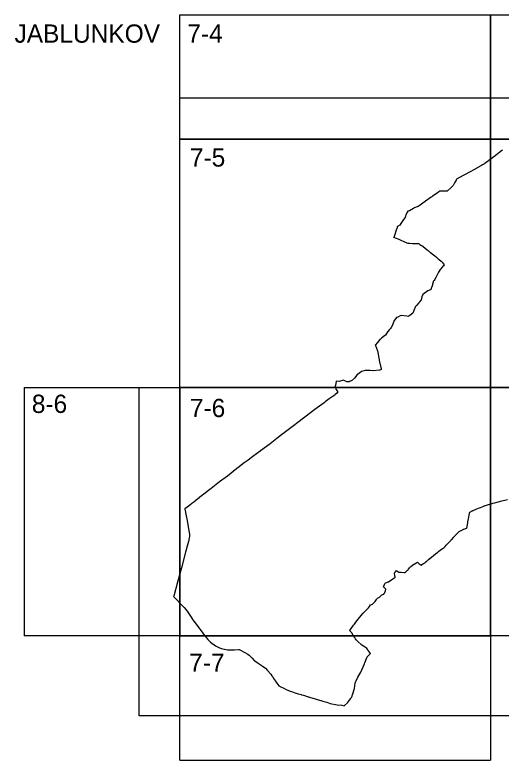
# Model space of a CAD drawing. Extents: x -449577 to -436680, y -1132317 to -1125726.
# Drawn here: x -441662.8 to -441418.4, y -1131943.6 to -1131568.6 of the extents above; entities that cross this region are included whole.
import ezdxf

# ---------------------------------------------------------------- set-up
doc = ezdxf.new("R2010")
doc.units = 0
for name, color, linetype in [('Vrstva 1', 7, 'Continuous'), ('Vrstva 10', 7, 'Continuous'), ('Vrstva 4', 7, 'Continuous')]:
    doc.layers.add(name, color=color, linetype=linetype)

msp = doc.modelspace()

# ---------------------------------------------------------------- linework, layer by layer
at = {"layer": 'Vrstva 1'}
for points in [[(-441417.64, -1131636.64), (-441418.85, -1131637.6), (-441418.85, -1131637.6), (-441420, -1131638.47), (-441420.57, -1131638.9), (-441421.15, -1131639.34), (-441421.31, -1131639.46), (-441423.44, -1131641.1), (-441424.51, -1131641.92), (-441424.98, -1131642.26), (-441425.74, -1131642.77), (-441425.99, -1131642.93), (-441426.58, -1131643.32), (-441426.62, -1131643.35), (-441426.83, -1131643.49), (-441427.74, -1131644.09), (-441427.75, -1131644.09), (-441428.22, -1131644.35), (-441428.37, -1131644.43), (-441428.55, -1131644.53), (-441429.01, -1131644.78), (-441429.19, -1131644.89), (-441429.35, -1131644.98), (-441429.45, -1131645.04), (-441429.69, -1131645.18), (-441431.35, -1131646.12), (-441431.52, -1131646.21), (-441431.75, -1131646.34), (-441434.22, -1131647.74), (-441434.34, -1131647.81), (-441436.45, -1131648.94), (-441437.47, -1131649.49), (-441440.81, -1131651.3), (-441440.98, -1131651.6), (-441441.04, -1131651.71), (-441441.82, -1131653.17), (-441442.5, -1131654.49), (-441442.64, -1131654.62), (-441442.73, -1131654.7), (-441443.87, -1131655.74), (-441445.38, -1131657.12), (-441445.55, -1131657.27), (-441445.55, -1131657.28), (-441446.02, -1131657.29), (-441449.21, -1131657.38), (-441449.22, -1131657.38), (-441449.65, -1131657.67), (-441450.48, -1131658.24), (-441452.95, -1131659.9), (-441452.99, -1131659.92), (-441453.23, -1131660.1), (-441453.5, -1131660.3), (-441456.48, -1131662.43), (-441456.55, -1131662.48), (-441459.55, -1131664.66), (-441460.02, -1131665), (-441460.18, -1131665.06), (-441462.12, -1131665.78), (-441462.13, -1131665.78), (-441462.52, -1131666.02), (-441464.4, -1131667.18), (-441465.32, -1131667.39), (-441465.57, -1131667.9), (-441466.33, -1131669.41), (-441466.34, -1131669.42), (-441466.41, -1131669.68), (-441466.61, -1131670.52), (-441467.44, -1131671.63), (-441468.81, -1131673.58), (-441469.37, -1131674.39), (-441469.4, -1131674.41), (-441470.56, -1131675.05), (-441470.66, -1131675.11), (-441470.73, -1131675.5), (-441470.88, -1131676.31), (-441470.93, -1131676.5), (-441472.22, -1131680.08), (-441472.39, -1131680.56), (-441472.36, -1131680.55), (-441472.34, -1131680.54), (-441471.66, -1131680.8), (-441469.85, -1131681.46), (-441469.23, -1131681.75), (-441466.94, -1131682.83), (-441466.92, -1131682.83), (-441465.76, -1131683.3), (-441465.29, -1131683.48), (-441465.26, -1131683.49), (-441464.83, -1131683.52), (-441464.69, -1131683.53), (-441464.47, -1131683.55), (-441462.87, -1131683.65), (-441461.83, -1131683.72), (-441460.78, -1131683.69), (-441459.94, -1131683.66), (-441459.93, -1131683.66), (-441459.65, -1131683.81), (-441459.28, -1131684.07), (-441458.73, -1131684.45), (-441458.34, -1131684.73), (-441456.78, -1131685.87), (-441456.61, -1131685.99), (-441455.5, -1131686.91), (-441455.11, -1131687.23), (-441454.93, -1131687.38), (-441454.18, -1131687.99), (-441453.91, -1131688.22), (-441453.31, -1131688.71), (-441453.09, -1131688.89), (-441452.45, -1131689.31), (-441451.7, -1131689.81), (-441451.67, -1131689.83), (-441450.91, -1131690.51), (-441450.03, -1131691.29), (-441449.59, -1131691.67), (-441448.58, -1131692.56), (-441448.32, -1131692.79), (-441448.27, -1131692.84), (-441448.17, -1131692.94), (-441448.16, -1131692.95), (-441448.07, -1131693.05), (-441448.04, -1131693.08), (-441446.99, -1131694.31), (-441447, -1131694.32), (-441447.44, -1131694.81), (-441447.5, -1131694.88), (-441448.07, -1131695.51), (-441448.89, -1131696.57), (-441449.06, -1131696.78), (-441449.62, -1131697.5), (-441449.92, -1131698.03), (-441449.94, -1131698.07), (-441449.95, -1131698.09), (-441450.08, -1131698.37), (-441450.88, -1131700.04), (-441451.19, -1131700.68), (-441451.81, -1131701.97), (-441451.92, -1131702.21), (-441451.93, -1131702.21), (-441451.97, -1131702.24), (-441452.26, -1131702.44), (-441452.34, -1131702.48), (-441452.39, -1131702.58), (-441452.48, -1131702.78), (-441452.57, -1131703.06), (-441452.74, -1131703.62), (-441452.75, -1131703.64), (-441452.87, -1131704.14), (-441452.89, -1131704.21), (-441452.88, -1131704.27), (-441452.87, -1131704.35), (-441452.87, -1131704.42), (-441452.88, -1131704.47), (-441453.76, -1131706.8), (-441453.78, -1131706.85), (-441453.8, -1131706.89), (-441453.81, -1131706.9), (-441454.51, -1131707.2), (-441454.76, -1131707.31), (-441455.23, -1131707.55), (-441457.84, -1131709.24), (-441457.84, -1131709.24), (-441458.21, -1131710.55), (-441458.29, -1131710.81), (-441458.4, -1131711.23), (-441458.46, -1131711.44), (-441458.46, -1131711.45), (-441458.45, -1131711.45), (-441458.28, -1131711.61), (-441458.29, -1131711.62), (-441458.65, -1131712.01), (-441459.45, -1131713.01), (-441459.46, -1131713.02), (-441459.67, -1131713.27), (-441459.67, -1131713.28), (-441459.79, -1131713.43), (-441460.95, -1131714.78), (-441461.49, -1131715.41), (-441462.25, -1131717.36), (-441462.63, -1131718.38), (-441462.76, -1131718.73), (-441464.29, -1131719.83), (-441464.91, -1131720.27), (-441465.09, -1131720.31), (-441465.11, -1131720.31), (-441465.74, -1131720.22), (-441468.58, -1131719.8), (-441469.07, -1131720.04), (-441470.4, -1131720.68), (-441470.94, -1131720.94), (-441470.97, -1131720.97), (-441471.4, -1131721.38), (-441471.57, -1131721.6), (-441472.23, -1131722.45), (-441472.23, -1131722.46), (-441472.9, -1131724.26), (-441473.47, -1131725.76), (-441473.47, -1131725.76), (-441473.61, -1131725.98), (-441473.94, -1131726.35), (-441474.66, -1131727.15), (-441475.36, -1131727.92), (-441475.37, -1131727.94), (-441475.5, -1131728.13), (-441476.57, -1131729.7), (-441477.04, -1131730.08), (-441478.61, -1131731.34), (-441479.28, -1131731.88), (-441479.38, -1131731.96), (-441479.41, -1131732), (-441480.53, -1131733.43), (-441481.67, -1131734.74), (-441481.52, -1131734.91), (-441481.51, -1131734.94), (-441481.51, -1131734.95), (-441480.5, -1131737.71), (-441480.22, -1131739.37), (-441479.9, -1131741.32), (-441479.49, -1131743.28), (-441478.76, -1131746.78), (-441478.72, -1131746.98), (-441479.37, -1131747.32), (-441479.49, -1131747.39), (-441482.66, -1131747.65), (-441482.82, -1131747.65), (-441484.31, -1131747.62), (-441486.7, -1131747.6), (-441487.98, -1131747.87), (-441488.58, -1131748.14), (-441489.56, -1131748.94), (-441490.86, -1131749.81), (-441490.95, -1131749.92), (-441492.11, -1131751.34), (-441493.56, -1131752.68), (-441494.25, -1131753), (-441494.85, -1131753.28), (-441496.02, -1131753.21), (-441497.63, -1131752.36), (-441499.87, -1131753.03), (-441501.35, -1131753), (-441501.73, -1131755.11), (-441501.74, -1131755.13), (-441501.75, -1131755.22), (-441501.46, -1131757.03), (-441500.49, -1131758.35), (-441500.48, -1131758.37), (-441501.22, -1131759.12), (-441501.83, -1131759.68), (-441502.08, -1131759.91), (-441502.88, -1131760.54), (-441504.81, -1131761.77), (-441504.87, -1131761.81), (-441506.84, -1131763.34), (-441506.9, -1131763.38), (-441507.39, -1131763.76), (-441512.05, -1131767.22), (-441512.08, -1131767.25), (-441517.03, -1131771.01), (-441521.29, -1131774.26), (-441522.17, -1131774.92), (-441524.74, -1131776.86), (-441528.74, -1131779.99), (-441531.18, -1131781.86), (-441534.49, -1131784.39), (-441534.54, -1131784.43), (-441539.33, -1131787.94), (-441539.56, -1131788.12), (-441543.17, -1131790.8), (-441545.56, -1131792.62), (-441547.53, -1131794.1), (-441549.85, -1131795.85), (-441550.08, -1131796.02), (-441551.21, -1131796.91), (-441556.03, -1131800.71), (-441559.92, -1131803.66), (-441564.14, -1131806.91), (-441565.43, -1131807.91), (-441567.82, -1131809.79), (-441569, -1131810.71), (-441572.94, -1131813.76), (-441573.87, -1131814.47), (-441575.11, -1131815.43), (-441577.43, -1131817.23), (-441577.43, -1131817.23), (-441577.39, -1131817.41), (-441577.1, -1131818.79), (-441577.07, -1131818.95), (-441576.54, -1131821.49), (-441576.38, -1131822.22), (-441576.38, -1131822.26), (-441575.45, -1131828.14), (-441575.44, -1131828.17), (-441575.14, -1131829.9), (-441575.14, -1131829.92), (-441575.08, -1131830.29), (-441575.02, -1131830.71), (-441575.05, -1131831.08), (-441575.2, -1131831.81), (-441575.58, -1131833.6), (-441575.87, -1131834.78), (-441575.89, -1131834.83), (-441577, -1131839), (-441579.1, -1131846.88), (-441581.09, -1131854.1), (-441583.02, -1131861.2), (-441583.03, -1131861.24), (-441577.75, -1131866.84), (-441576.7, -1131867.97), (-441575.94, -1131869.19), (-441573.92, -1131872.25), (-441573.87, -1131872.32), (-441572.86, -1131873.73), (-441572.7, -1131873.94), (-441570.82, -1131876.42), (-441570.25, -1131877.16), (-441570.22, -1131877.2), (-441569.7, -1131877.92), (-441568.32, -1131879.82), (-441567.99, -1131880.27), (-441565.84, -1131882.99), (-441564.44, -1131884.21), (-441562.04, -1131886.19), (-441560.3, -1131886.94), (-441559.11, -1131887.46), (-441558.98, -1131887.51), (-441557.65, -1131887.79), (-441557.51, -1131887.82), (-441555.89, -1131888.15), (-441555.86, -1131888.15), (-441554.9, -1131888.13), (-441554.52, -1131888.13), (-441554, -1131888.12), (-441553.32, -1131888.11), (-441552.41, -1131888.07), (-441550.46, -1131887.91), (-441550.01, -1131887.98), (-441549.35, -1131888.33), (-441547.63, -1131889.28), (-441545.67, -1131890.38), (-441545.15, -1131890.86), (-441544.43, -1131891.54), (-441543.63, -1131892.29), (-441542.31, -1131893.59), (-441542.17, -1131893.69), (-441540.98, -1131894.54), (-441538.57, -1131896.25), (-441536.93, -1131897.43), (-441535.88, -1131898.61), (-441534.24, -1131900.43), (-441533.6, -1131901.14), (-441533.24, -1131901.73), (-441532.78, -1131902.47), (-441531.84, -1131903.94), (-441531.21, -1131904.86), (-441530.17, -1131906.3), (-441529.1, -1131906.81), (-441527.72, -1131907.46), (-441526.41, -1131908.07), (-441524.44, -1131908.96), (-441523.31, -1131909.31), (-441521.59, -1131909.88), (-441521.44, -1131909.93), (-441520.35, -1131910.25), (-441518.93, -1131910.67), (-441518.92, -1131910.67), (-441518.71, -1131910.73), (-441518.65, -1131910.75), (-441517.79, -1131911.01), (-441515.4, -1131911.7), (-441515.28, -1131911.74), (-441514.8, -1131911.88), (-441511.87, -1131912.75), (-441509.18, -1131913.58), (-441508.84, -1131913.68), (-441508.08, -1131913.91), (-441506.07, -1131914.53), (-441504.34, -1131915.08), (-441500.88, -1131915.82)], [(-441500.88, -1131915.82), (-441498.49, -1131916.01), (-441497.29, -1131916.24), (-441497.18, -1131916.15), (-441495.6, -1131914.88), (-441494.57, -1131913.4), (-441494.46, -1131913.25), (-441493.94, -1131912.49), (-441493.83, -1131912.32), (-441493.69, -1131912.09), (-441493.31, -1131911.46), (-441493.04, -1131910.63), (-441493.02, -1131910.56), (-441493, -1131910.51), (-441492.97, -1131910.4), (-441492.94, -1131910.31), (-441492.94, -1131910.3), (-441492.31, -1131908.1), (-441492.17, -1131907.58), (-441491.72, -1131904.83), (-441491.72, -1131904.83), (-441491.53, -1131904.39), (-441491.27, -1131903.77), (-441490.48, -1131901.94), (-441488.91, -1131899.29), (-441487.16, -1131895.16), (-441486.84, -1131894.52), (-441486.8, -1131894.39), (-441486.41, -1131893.29), (-441485.82, -1131891.62), (-441484.14, -1131889.91), (-441485.07, -1131888.67), (-441485.13, -1131888.58), (-441485.18, -1131888.52), (-441485.21, -1131888.48), (-441485.28, -1131888.38), (-441485.33, -1131888.3), (-441485.41, -1131888.18), (-441485.77, -1131887.66), (-441486.14, -1131887.2), (-441486.71, -1131886.83), (-441486.81, -1131886.77), (-441488.46, -1131885.7), (-441490.65, -1131883.76), (-441490.78, -1131883.59), (-441490.81, -1131883.55), (-441490.89, -1131883.45), (-441491.23, -1131883.03), (-441491.56, -1131882.62), (-441491.82, -1131882.3), (-441492.3, -1131881.71), (-441492.38, -1131881.61), (-441492.88, -1131880.65), (-441493.17, -1131880.09), (-441493.4, -1131879.66), (-441493.45, -1131879.57), (-441493.49, -1131879.52), (-441493.75, -1131879.23), (-441493.95, -1131879), (-441494.21, -1131878.71), (-441494.43, -1131878.46), (-441492.57, -1131875.72), (-441492.48, -1131875.6), (-441492.16, -1131875.15), (-441491.84, -1131874.71), (-441490.51, -1131872.88), (-441487.83, -1131869.62), (-441487.48, -1131869.3), (-441486.77, -1131868.6), (-441486.66, -1131868.51), (-441486.47, -1131868.37), (-441485.87, -1131867.89), (-441485.01, -1131867.05), (-441484.6, -1131866.29), (-441484.13, -1131865.42), (-441483.08, -1131865.18), (-441481.68, -1131863.75), (-441481.14, -1131862.9), (-441481.13, -1131862.89), (-441481.13, -1131862.87), (-441480.92, -1131862.54), (-441480.87, -1131862.46), (-441480.63, -1131862.07), (-441479.47, -1131861.63), (-441478.45, -1131860.45), (-441477.92, -1131860.25), (-441477.8, -1131860.2), (-441477.38, -1131860.04), (-441477.16, -1131859.65), (-441477.11, -1131859.56), (-441476.94, -1131859.26), (-441476.53, -1131858.52), (-441476.33, -1131857.61), (-441476.33, -1131857.59), (-441476.32, -1131857.58), (-441477.37, -1131856.59), (-441477.39, -1131856.58), (-441477.4, -1131856.56), (-441477.45, -1131856.52), (-441476.8, -1131854.72), (-441476.73, -1131854.52), (-441476.57, -1131854.46), (-441475.84, -1131854.17), (-441475.15, -1131853.9), (-441475.03, -1131853.85), (-441473.82, -1131853.14), (-441473.7, -1131853.06), (-441473.7, -1131853.06), (-441473.69, -1131853.05), (-441473.57, -1131852.98), (-441471.71, -1131851.58), (-441471.71, -1131851.54), (-441471.74, -1131851.38), (-441471.81, -1131850.9), (-441471.87, -1131850.55), (-441471.97, -1131849.93), (-441471.99, -1131849.82), (-441472.01, -1131849.69), (-441472.03, -1131849.52), (-441472.06, -1131849.38), (-441471.52, -1131848.82), (-441470.96, -1131848.25), (-441470.92, -1131848.2), (-441470.78, -1131848.3), (-441469.78, -1131849.09), (-441469.1, -1131849.1), (-441469.04, -1131849.1), (-441468.79, -1131849.11), (-441468.63, -1131849.11), (-441467.32, -1131849.13), (-441466.69, -1131849.15), (-441466.42, -1131848.99), (-441466.39, -1131848.97), (-441466.27, -1131848.9), (-441466.13, -1131848.81), (-441466.09, -1131848.78), (-441465.55, -1131848.18), (-441465.44, -1131848.06), (-441465.35, -1131847.96), (-441465.18, -1131847.78), (-441465.1, -1131847.69), (-441464.99, -1131847.57), (-441464.96, -1131847.53), (-441464.93, -1131847.5), (-441464.88, -1131847.44), (-441464.79, -1131847.33), (-441464.39, -1131846.83), (-441464.18, -1131846.57), (-441463.93, -1131846.25), (-441463.82, -1131846.17), (-441462.36, -1131845.1), (-441462.15, -1131844.97), (-441460.79, -1131844.2), (-441460.39, -1131843.97), (-441460.39, -1131843.97), (-441460.25, -1131844.12), (-441459.54, -1131844.83), (-441459.17, -1131845.21), (-441458.99, -1131845.38), (-441458.84, -1131845.53), (-441458.75, -1131845.49), (-441457.47, -1131844.72), (-441457.38, -1131844.67), (-441456.45, -1131844.11), (-441456.41, -1131844.08), (-441456.08, -1131843.79), (-441456.03, -1131843.75), (-441455.86, -1131843.6), (-441455.85, -1131843.59), (-441455.85, -1131843.59), (-441455.81, -1131843.55), (-441455.77, -1131843.51), (-441454.88, -1131842.7), (-441454.86, -1131842.69), (-441454.27, -1131842.15), (-441454.16, -1131842.06), (-441454.05, -1131841.96), (-441454.05, -1131841.96), (-441454.04, -1131841.96), (-441454.04, -1131841.96), (-441454.04, -1131841.95), (-441454.03, -1131841.95), (-441454.02, -1131841.94), (-441454.02, -1131841.94), (-441454.01, -1131841.93), (-441454.01, -1131841.93), (-441454, -1131841.93), (-441454, -1131841.93), (-441453.42, -1131841.44), (-441451.43, -1131839.76), (-441450.23, -1131838.91), (-441450.11, -1131838.83), (-441450.06, -1131838.79), (-441450.04, -1131838.78), (-441449.99, -1131838.75), (-441449.63, -1131838.48), (-441448.39, -1131837.54), (-441448.21, -1131837.4), (-441448, -1131837.24), (-441447.98, -1131837.22), (-441447.1, -1131836.55), (-441446.75, -1131836.28), (-441446.7, -1131836.22), (-441446.61, -1131836.12), (-441445.97, -1131835.44), (-441445.07, -1131834.46), (-441443.71, -1131833.05), (-441443.49, -1131832.82), (-441443.24, -1131832.54), (-441442.4, -1131831.59), (-441442.11, -1131831.27), (-441441.91, -1131831.06), (-441441.62, -1131830.74), (-441440.44, -1131829.55), (-441439.51, -1131828.53), (-441437.45, -1131827.52), (-441437.29, -1131827.47), (-441437.09, -1131827.39), (-441435.65, -1131826.9), (-441435.5, -1131826.03), (-441435.34, -1131825.16), (-441434.92, -1131822.79), (-441434.84, -1131822.32), (-441434.51, -1131820.44), (-441434.31, -1131819.56), (-441434.28, -1131819.44), (-441434.23, -1131819.25), (-441434.22, -1131819.21), (-441434.2, -1131819.14), (-441434.19, -1131819.1), (-441434.18, -1131819.05), (-441434.17, -1131819.01), (-441434.16, -1131818.99), (-441434.1, -1131818.78), (-441433.02, -1131818.24), (-441432.73, -1131818.1), (-441432.71, -1131818.09), (-441432.46, -1131817.96), (-441432.41, -1131817.94), (-441430.64, -1131817.22), (-441430.61, -1131817.21), (-441430.58, -1131817.19), (-441429.78, -1131816.88), (-441428.82, -1131816.48), (-441428.01, -1131816.14), (-441427.07, -1131815.75), (-441426.99, -1131815.72), (-441426.38, -1131815.48), (-441426.53, -1131815.64), (-441426.29, -1131815.55), (-441425.8, -1131815.35), (-441425.27, -1131815.19), (-441423.57, -1131814.67), (-441422.98, -1131814.5), (-441422.53, -1131814.38), (-441421.64, -1131814.13), (-441420.33, -1131813.75), (-441418.79, -1131813.29), (-441415.25, -1131812.42)]]:
    msp.add_lwpolyline(points, dxfattribs=at)
at = {"layer": 'Vrstva 10'}
msp.add_lwpolyline([(-441267.49, -1131610.43), (-441267.49, -1131921.41), (-441600.36, -1131921.41), (-441600.36, -1131756.11), (-441579.99, -1131756.11), (-441579.99, -1131631.11), (-441579.99, -1131610.43), (-441267.49, -1131610.43)], dxfattribs=at)
at = {"layer": 'Vrstva 4'}
for p, q in [((-441579.99, -1131568.61), (-441267.49, -1131568.61)), ((-441658.12, -1131756.11), (-441658.12, -1131881.11)), ((-441579.99, -1131943.61), (-441423.74, -1131943.61))]:
    msp.add_line(p, q, dxfattribs=at)
for points in [[(-441423.74, -1131568.61), (-441423.74, -1131631.11), (-441579.99, -1131631.11), (-441579.99, -1131568.61)], [(-441267.49, -1131568.61), (-441267.49, -1131631.11), (-441423.74, -1131631.11), (-441423.74, -1131568.61)], [(-441658.12, -1131756.11), (-441579.99, -1131756.11), (-441579.99, -1131881.11), (-441658.12, -1131881.11)], [(-441579.99, -1131943.61), (-441579.99, -1131881.11), (-441423.74, -1131881.11), (-441423.74, -1131943.61)]]:
    msp.add_lwpolyline(points, dxfattribs=at)
for points in [[(-441423.74, -1131631.11), (-441423.74, -1131756.11), (-441579.99, -1131756.11), (-441579.99, -1131631.11)], [(-441267.49, -1131631.11), (-441267.49, -1131756.11), (-441423.74, -1131756.11), (-441423.74, -1131631.11)], [(-441423.74, -1131756.11), (-441423.74, -1131881.11), (-441579.99, -1131881.11), (-441579.99, -1131756.11)], [(-441267.49, -1131756.11), (-441267.49, -1131881.11), (-441423.74, -1131881.11), (-441423.74, -1131756.11)]]:
    msp.add_lwpolyline(points, close=True, dxfattribs=at)

# ---------------------------------------------------------------- texts
at = {"layer": 'Vrstva 1'}
for s, p in [('JABLUNKOV', (-441663.03, -1131582.61)), ('7-4', (-441576.18, -1131582.61)), ('7-5', (-441574.87, -1131644.95)), ('8-6', (-441654.34, -1131768.92)), ('7-6', (-441574.87, -1131771.02)), ('7-7', (-441575.23, -1131899.19))]:
    msp.add_text(s, height=9.2, dxfattribs=at).set_placement(p)

doc.saveas('drawing.dxf')
